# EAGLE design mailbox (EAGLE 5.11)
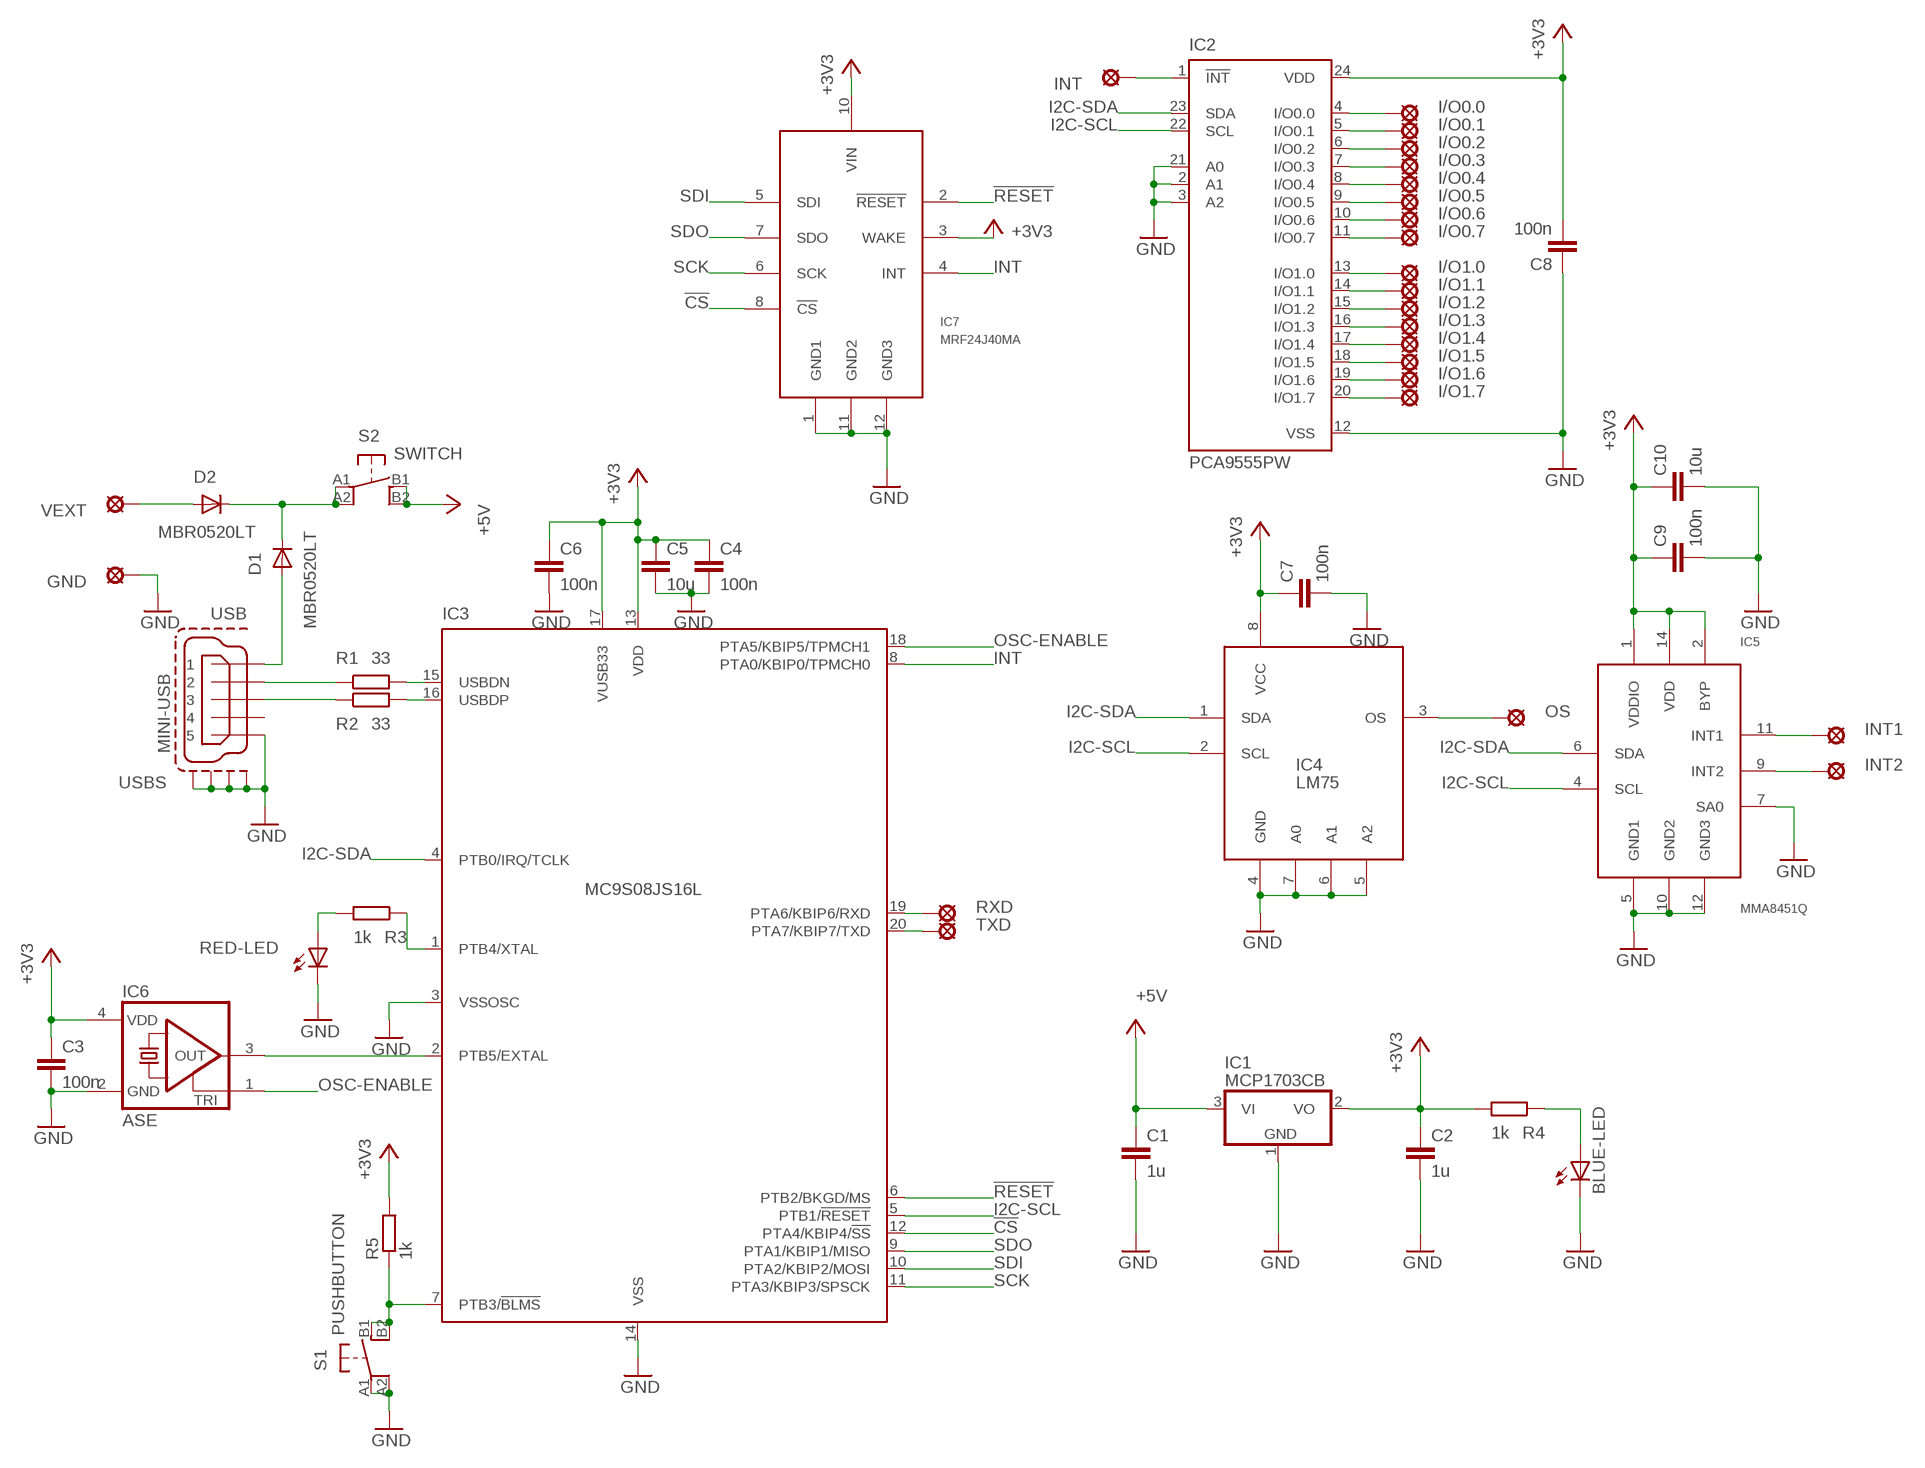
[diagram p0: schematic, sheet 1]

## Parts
BLUE-LED  LED5MM  [LED5MM]
C1  1u  C-EUC1210  [C1210]
C2  1u  C-EUC1210  [C1210]
C3  100n  C-EUC0603  [C0603]
C4  100n  C-EUC0603  [C0603]
C5  10u  C-EUC1210  [C1210]
C6  100n  C-EUC0603  [C0603]
C7  100n  C-EUC0603  [C0603]
C8  100n  C-EUC0603  [C0603]
C9  100n  C-EUC0603  [C0603]
C10  10u  C-EUC1210  [C1210]
D1  MBR0520LT  [SOD123]
D2  MBR0520LT  [SOD123]
GND  LSP10  [LSP10]
I/O0.0  LSP10  [LSP10]
I/O0.1  LSP10  [LSP10]
I/O0.2  LSP10  [LSP10]
I/O0.3  LSP10  [LSP10]
I/O0.4  LSP10  [LSP10]
I/O0.5  LSP10  [LSP10]
I/O0.6  LSP10  [LSP10]
I/O0.7  LSP10  [LSP10]
I/O1.0  LSP10  [LSP10]
I/O1.1  LSP10  [LSP10]
I/O1.2  LSP10  [LSP10]
I/O1.3  LSP10  [LSP10]
I/O1.4  LSP10  [LSP10]
I/O1.5  LSP10  [LSP10]
I/O1.6  LSP10  [LSP10]
I/O1.7  LSP10  [LSP10]
IC1  MCP1703CB  [SOT23]
IC2  PCA9555PW  [TSSOP24]
IC3  MC9S08JS16L  [SO-20DW]
IC4  LM75  [SOIC8]
IC5  MMA8451Q  [QFN16]
IC6  ASE  [ASE]
IC7  MRF24J40MA  [MRF24J40MA]
INT  LSP10  [LSP10]
INT1  LSP10  [LSP10]
INT2  LSP10  [LSP10]
OS  LSP10  [LSP10]
R1  33  R-EU_R0805  [R0805]
R2  33  R-EU_R0805  [R0805]
R3  1k  R-EU_R0805  [R0805]
R4  1k  R-EU_R0805  [R0805]
R5  1k  R-EU_R0805  [R0805]
RED-LED  LED5MM  [LED5MM]
RXD  LSP10  [LSP10]
S1  PUSHBUTTON  [PUSHBUTTON]
S2  SWITCH  [SWITCH]
TXD  LSP10  [LSP10]
USB  MINI-USB  MINI-USB-SHIELD-UX60-MB-5ST  [TYCO]
VEXT  LSP10  [LSP10]

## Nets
!CS: IC3.12(PTA4/KBIP4/!SS) IC7.8(!CS)
!RESET: IC3.6(PTB2/BKGD/MS) IC7.2(!RESET)
+3V3: C2.1 C3.1 C4.1 C5.1 C6.1 C7.1 C8.2 C9.1 C10.1 IC1.2(VO) IC2.24(VDD) IC3.13(VDD) IC3.17(VUSB33) IC4.8(VCC) IC5.1(VDDIO) IC5.2(BYP) IC5.14(VDD) IC6.4(VDD) IC7.3(WAKE) IC7.10(VIN) R4.2 R5.2
+5V: C1.1 IC1.3(VI) S2.B1(S) S2.B2(S1)
GND: BLUE-LED.K(C) C1.2 C2.2 C3.2 C4.2 C5.2 C6.2 C7.2 C8.1 C9.2 C10.2 GND.MP IC1.1(GND) IC2.2(A1) IC2.3(A2) IC2.12(VSS) IC2.21(A0) IC3.3(VSSOSC) IC3.14(VSS) IC4.4(GND) IC4.5(A2) IC4.6(A1) IC4.7(A0) IC5.5(GND1) IC5.7(SA0) IC5.10(GND2) IC5.12(GND3) IC6.2(GND) IC7.1(GND1) IC7.11(GND2) IC7.12(GND3) RED-LED.K(C) S1.A1(P) S1.A2(P1) USB.5 USB.M1(S1) USB.M2(S2) USB.M3(S3) USB.M4(S4)
I2C-SCL: IC2.22(SCL) IC3.5(PTB1/!RESET) IC4.2(SCL) IC5.4(SCL)
I2C-SDA: IC2.23(SDA) IC3.4(PTB0/IRQ/TCLK) IC4.1(SDA) IC5.6(SDA)
INT: IC3.8(PTA0/KBIP0/TPMCH0) IC7.4(INT)
N$1: R1.1 USB.2
N$2: IC3.2(PTB5/EXTAL) IC6.3(OUT)
N$3: IC3.1(PTB4/XTAL) R3.1
N$4: BLUE-LED.A R4.1
N$5: D1.A USB.1
N$6: R2.1 USB.3
N$7: IC3.15(USBDN) R1.2
N$8: IC3.16(USBDP) R2.2
N$9: R3.2 RED-LED.A
N$10: I/O0.0.MP IC2.4(I/O0.0)
N$11: I/O0.1.MP IC2.5(I/O0.1)
N$12: I/O0.2.MP IC2.6(I/O0.2)
N$13: IC3.19(PTA6/KBIP6/RXD) RXD.MP
N$14: IC3.20(PTA7/KBIP7/TXD) TXD.MP
N$15: I/O0.3.MP IC2.7(I/O0.3)
N$16: I/O0.4.MP IC2.8(I/O0.4)
N$17: I/O0.5.MP IC2.9(I/O0.5)
N$18: I/O0.6.MP IC2.10(I/O0.6)
N$19: I/O0.7.MP IC2.11(I/O0.7)
N$20: I/O1.0.MP IC2.13(I/O1.0)
N$21: I/O1.1.MP IC2.14(I/O1.1)
N$22: I/O1.2.MP IC2.15(I/O1.2)
N$23: I/O1.3.MP IC2.16(I/O1.3)
N$24: I/O1.4.MP IC2.17(I/O1.4)
N$25: I/O1.5.MP IC2.18(I/O1.5)
N$26: I/O1.6.MP IC2.19(I/O1.6)
N$27: I/O1.7.MP IC2.20(I/O1.7)
N$28: IC4.3(OS) OS.MP
N$29: IC5.11(INT1) INT1.MP
N$30: IC5.9(INT2) INT2.MP
N$31: IC2.1(!INT) INT.MP
N$33: D1.C D2.C S2.A1(P) S2.A2(P1)
N$34: D2.A VEXT.MP
N$35: IC3.7(PTB3/!BLMS) R5.1 S1.B1(S) S1.B2(S1)
OSC-ENABLE: IC3.18(PTA5/KBIP5/TPMCH1) IC6.1(TRI)
SCK: IC3.11(PTA3/KBIP3/SPSCK) IC7.6(SCK)
SDI: IC3.10(PTA2/KBIP2/MOSI) IC7.5(SDI)
SDO: IC3.9(PTA1/KBIP1/MISO) IC7.7(SDO)
Unconnected: USB.4

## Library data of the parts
BLUE-LED RED-LED = led:LED: LED
C1-C10 = rcl:C-EU: CAPACITOR, European symbol
D1 D2 = diode:MBR0520LT: SCHOTTKY BARRIER RECTIFIER
GND I/O0.0 I/O0.1-I/O0.7 I/O1.0 I/O1.1-I/O1.7 INT INT1 INT2 OS RXD TXD VEXT = solpad:LSP10: SOLDER PAD
IC1 = linear:MCP1703: 250 mA, 16V, Low Quiescent Current LDO Regulator Source: http://ww1.microchip.com/downloads/en/DeviceDoc/22049b.pdf
IC2 = micro-philips:PCA9555: 16-bit I2C and SMBus I/O port with interrupt Source: PCA9555_5.pdf; MPN: PCA9555PW; OC_FARNELL: 1408297; OC_NEWARK: 63K6069
IC3 = mailbox:MC9S08JS16L
IC4 = mailbox:LM75
IC5 = mailbox:MMA8451Q
IC6 = mailbox:ASE: 3.3Vdc CMOS SMD CRYSTAL CLOCK OSCILLATOR SOurce: www.abracon.com; OC_FARNELL: unknown; OC_NEWARK: unknown
IC7 = mailbox:MRF24J40MA
R1-R5 = rcl:R-EU_: RESISTOR, European symbol
S1 = mailbox:PUSHBUTTON
S2 = mailbox:SWITCH
USB = mailbox:MINI-USB-SHIELD-: MINI USB Connector Source: http://www.hirose.co.jp/cataloge_hp/e24000019.pdf; OC_FARNELL: unknown; OC_NEWARK: unknown

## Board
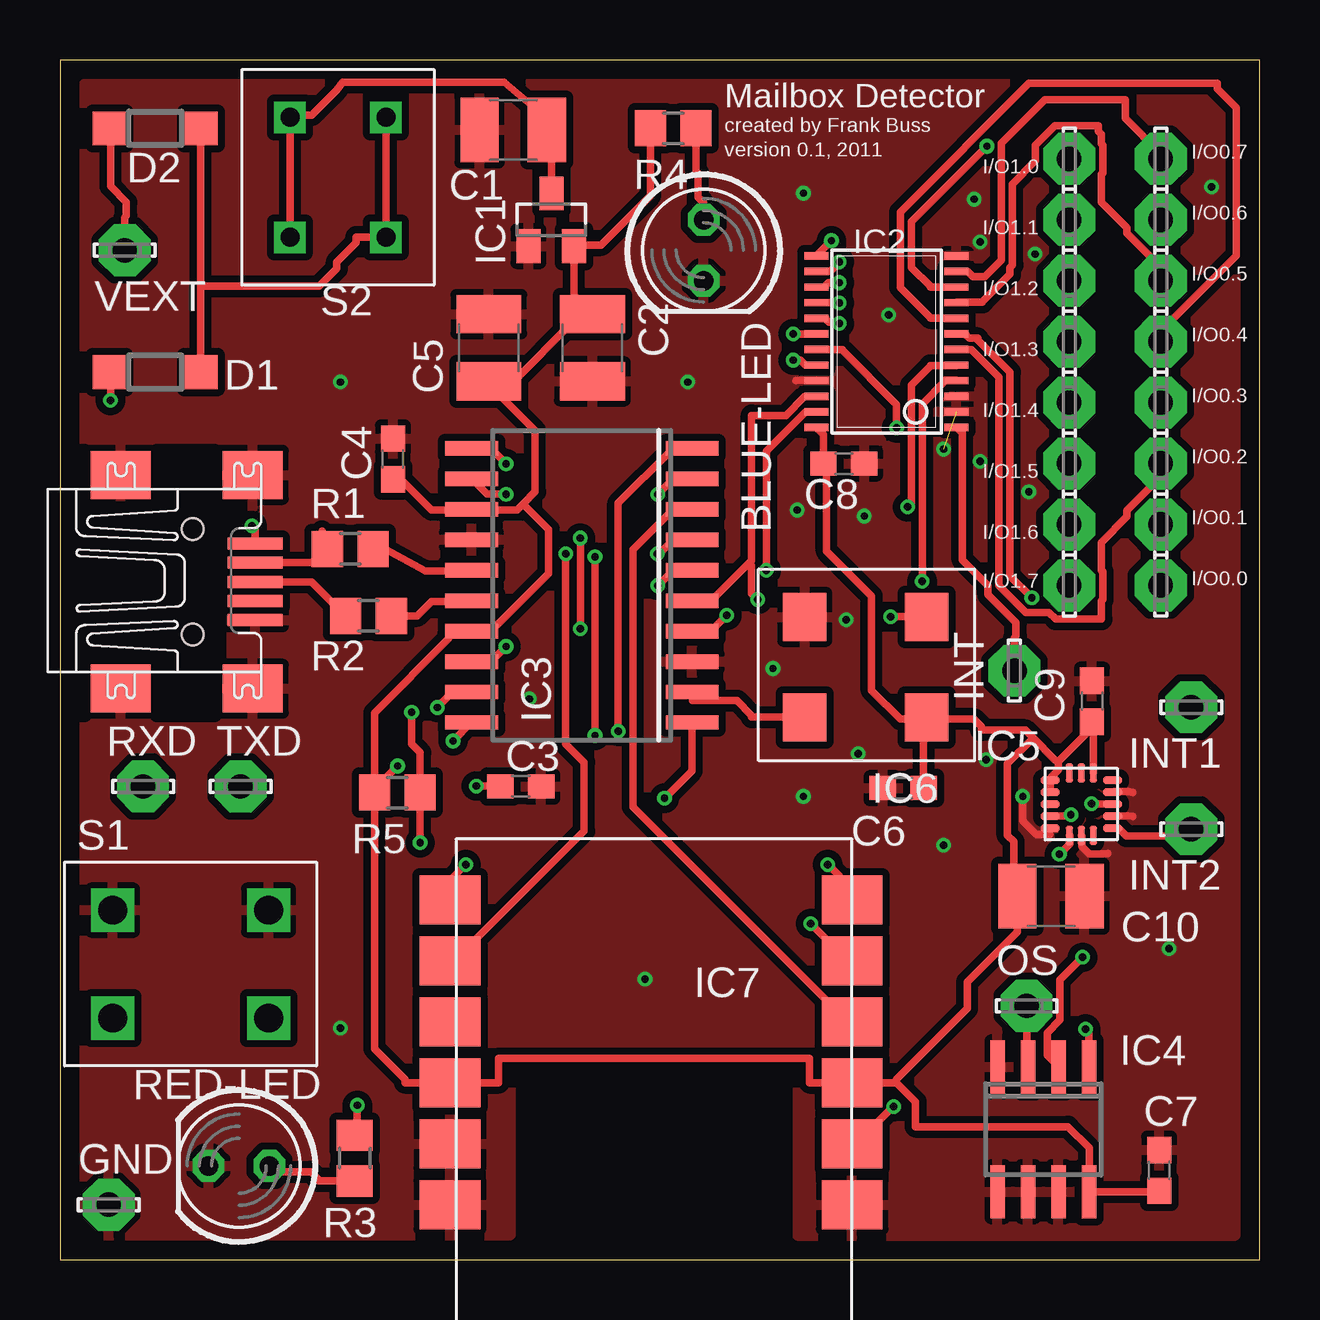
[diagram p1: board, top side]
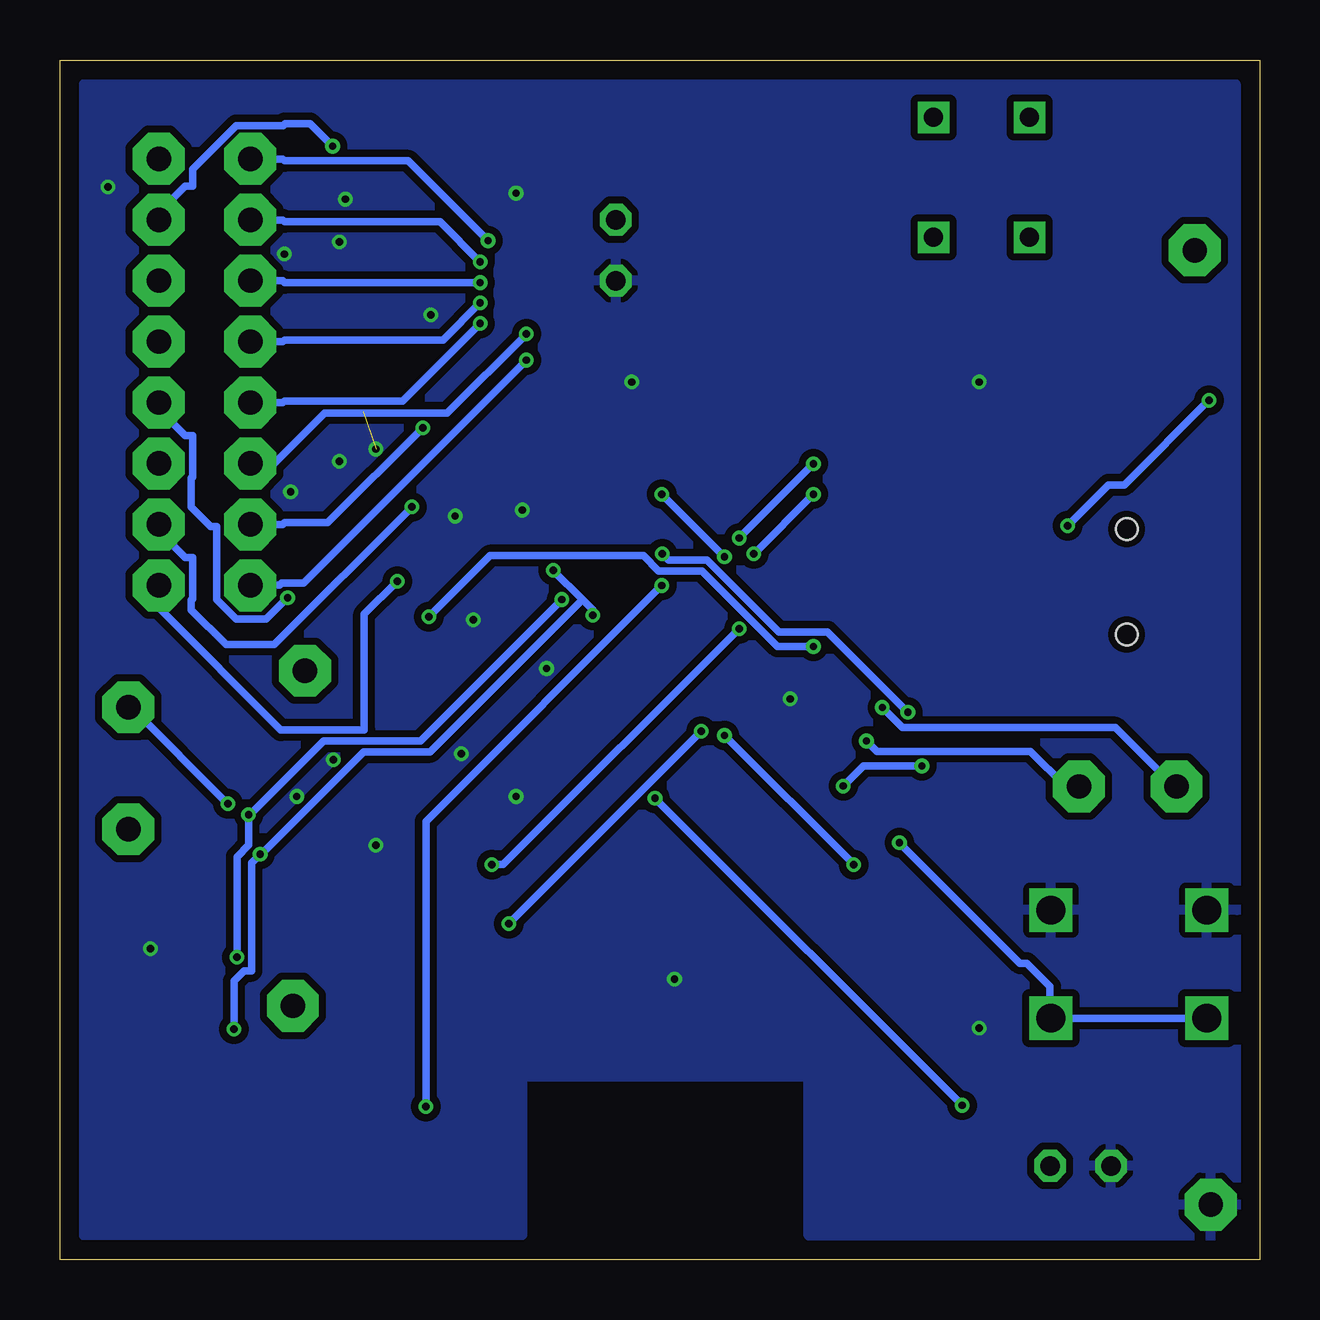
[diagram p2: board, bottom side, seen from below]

Size 50 x 50 mm. Coordinates in mm from the lower left corner, seen from the top.
Outline: 0,0 50,0 50,50 0,50 0,0
Copper layers (1*16): Top 0.035mm / dielectric 1.5mm / Bottom 0.035mm
Design rules "ITead_rule *": minimum track width 12mil, minimum drill 12mil, track to track 6mil, track to pad 6mil, pad to pad 6mil, via to via 6mil, smd to smd 0mil, copper to edge 10mil, drill to drill 10mil, minimum pad ring 10mil, minimum via ring 6mil, stop-mask expansion 2mil, vias tented up to drill 100mil, thermal gap 10mil

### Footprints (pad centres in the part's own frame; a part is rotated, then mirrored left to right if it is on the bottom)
LED5MM = drill 0.813 octagon: A -1.27,0; K 1.27,0
C1210 = smd 1.6 x 2.7: 1 -1.4,0; 2 1.4,0
C0603 = smd 1.1 x 1: 1 -0.85,0; 2 0.85,0
SOD123 = smd 1.4 x 1.4: A 1.9,0; C -1.9,0
LSP10 = drill 1.016 pad 2.159 octagon: MP 0,0
SOT23 = smd 1 x 1.4: 1 -0.95,-1.1; 2 0.95,-1.1; 3 0,1.1
TSSOP24 = smd 0.305 x 0.991: 1 -3.575,-2.918; 2 -2.925,-2.918; 3 -2.275,-2.918; 4 -1.625,-2.918; 5 -0.975,-2.918; 6 -0.325,-2.918; 7 0.325,-2.918; 8 0.975,-2.918; 9 1.625,-2.918; 10 2.275,-2.918; 11 2.925,-2.918; 12 3.575,-2.918; 13 3.575,2.918; 14 2.925,2.918; 15 2.275,2.918; 16 1.625,2.918; 17 0.975,2.918; 18 0.325,2.918; 19 -0.325,2.918; 20 -0.975,2.918; 21 -1.625,2.918; 22 -2.275,2.918; 23 -2.925,2.918; 24 -3.575,2.918
SO-20DW = smd 0.6 x 2.2: 1 -5.715,-4.6; 2 -4.445,-4.6; 3 -3.175,-4.6; 4 -1.905,-4.6; 5 -0.635,-4.6; 6 0.635,-4.6; 7 1.905,-4.6; 8 3.175,-4.6; 9 4.445,-4.6; 10 5.715,-4.6; 11 5.715,4.6; 12 4.445,4.6; 13 3.175,4.6; 14 1.905,4.6; 15 0.635,4.6; 16 -0.635,4.6; 17 -1.905,4.6; 18 -3.175,4.6; 19 -4.445,4.6; 20 -5.715,4.6
SOIC8 = smd 0.6 x 2.2: 1 -1.905,-2.6; 2 -0.635,-2.6; 3 0.635,-2.6; 4 1.905,-2.6; 5 1.905,2.6; 6 0.635,2.6; 7 -0.635,2.6; 8 -1.905,2.6
QFN16 = smd 0.8 x 0.3: 1 0.8,0.5; 2 0.8,1; 3 0.8,1.5; 4 0.8,2; 5 0.8,2.5; 9 -1.8,2.5; 10 -1.8,2; 11 -1.8,1.5; 12 -1.8,1; 13 -1.8,0.5 | smd 0.3 x 0.8: 6 0,2.8; 7 -0.5,2.8; 8 -1,2.8; 14 -1,0.2; 15 -0.5,0.2; 16 0,0.2
ASE = smd 1.8 x 2: 1 -2.5,-2.5; 2 2.58,-2.5; 3 2.58,1.7; 4 -2.5,1.7
MRF24J40MA = smd 2.54 x 2.032: 1 0,12.7; 2 0,10.16; 3 0,7.62; 4 0,5.08; 5 0,2.54; 6 0,0; 7 16.764,0; 8 16.764,2.54; 9 16.764,5.08; 10 16.764,7.62; 11 16.764,10.16; 12 16.764,12.7
R0805 = smd 1.3 x 1.5: 1 -0.95,0; 2 0.95,0
PUSHBUTTON = drill 1.2 square: A1 0,4.5; A2 6.5,4.5; B1 0,0; B2 6.5,0
SWITCH = drill 0.8 square: A1 -2,2; A2 -2,-3; B1 2,2; B2 2,-3
TYCO = smd 2.3 x 0.5: 1 2.9,1.75; 2 2.9,0.95; 3 2.9,0.15; 4 2.9,-0.65; 5 2.9,-1.45 | smd 2.5 x 2: M1 -2.7,-4.3; M2 -2.7,4.6; M3 2.8,4.6; M4 2.8,-4.3 | hole 0.9: 0.3,2.35; 0.3,-2.05

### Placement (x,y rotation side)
BLUE-LED  26.83,42.07 270 top
C1  18.89,47.08 180 top
C2  22.19,38.01 270 top
C3  19.21,19.72 0 top
C4  13.88,33.37 90 top
C5  17.87,38.01 90 top
C6  35.15,19.65 180 top
C7  45.81,3.72 90 top
C8  32.67,33.18 180 top
C9  43.02,23.27 90 top
C10  41.31,15.15 0 top
D1  3.97,36.99 180 top
D2  3.97,47.15 180 top
GND  2.03,2.29 0 top
I/O0.0  45.88,28.1 90 top
I/O0.1  45.88,30.64 90 top
I/O0.2  45.88,33.18 90 top
I/O0.3  45.88,35.72 90 top
I/O0.4  45.88,38.26 90 top
I/O0.5  45.88,40.8 90 top
I/O0.6  45.88,43.34 90 top
I/O0.7  45.88,45.88 90 top
I/O1.0  42.07,45.88 90 top
I/O1.1  42.07,43.34 90 top
I/O1.2  42.07,40.8 90 top
I/O1.3  42.07,38.26 90 top
I/O1.4  42.07,35.72 90 top
I/O1.5  42.07,33.18 90 top
I/O1.6  42.07,30.64 90 top
I/O1.7  42.07,28.1 90 top
IC1  20.48,43.34 0 top
IC2  34.45,38.26 90 top
IC3  21.75,28.1 90 top
IC4  40.99,5.43 180 top
IC5  42.07,20.48 180 top
IC6  33.62,24.29 180 top
IC7  33.02,14.99 180 top
INT  39.78,24.54 90 top
INT1  47.15,23.02 180 top
INT2  47.15,17.94 180 top
OS  40.29,10.57 0 top
R1  12.1,29.62 0 top
R2  12.86,26.83 0 top
R3  12.29,4.22 270 top
R4  25.56,47.15 180 top
R5  14.06,19.46 180 top
RED-LED  7.46,3.9 180 top
RXD  3.46,19.72 0 top
S1  2.19,10.07 0 top
S2  11.59,44.61 180 top
TXD  7.53,19.72 0 top
USB  5.24,28.1 0 top
VEXT  2.7,42.07 0 top

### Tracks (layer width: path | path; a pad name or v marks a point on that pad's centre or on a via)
!CS  (via drill 0.3)
  Top 0.305: v18.59,31.9 17.8,31.9 17.17,32.54 IC3.12 | v21.08,29.41 21.08,21.49 21.84,20.73 21.84,17.86 16.43,12.45 IC7.8
  Bottom 0.305: v21.08,29.41 v18.59,31.9
!RESET  (via drill 0.3)
  Top 0.305: v24.92,28.09 25.43,28.6 25.43,28.73 26.34,28.73 IC3.6 | v34.75,6.38 33.2,4.83 IC7.2
  Bottom 0.305: v24.92,28.09 34.75,18.26 v34.75,6.38
+3V3  (via drill 0.3)
  Top 0.305: C4.1 14.22,32.52 15.49,31.24 17.12,31.24 IC3.13 17.18,31.24 19.05,31.24 19.3,31.5 | C6.1 36,22.46 IC6.4 | IC2.24 31.82,34.4 C8.2 31.9,33.05 31.95,32.99 31.95,29.54 33.83,27.66 33.83,23.72 35.03,22.53 35.87,22.53 IC6.4 | IC5.14 43.07,22.37 C9.1 42.93,22.07 41.6,20.75 | C7.1 45.78,2.83 IC4.8 42.9,2.97 42.9,4.65 42.01,5.54 35.66,5.54 35.66,6.58 34.87,7.37 | 19.3,31.5 19.81,32 19.81,34.54 17.87,36.48 C5.1 18.44,36.12 18.44,36.14 21.84,39.55 C2.1 21.43,40.17 IC1.2 21.57,42.29 22.55,42.29 24.61,44.35 R4.2 | IC5.2 41.27,19.96 IC5.1 41.33,20.12 41.6,20.4 41.6,20.75 | 40.56,21.74 40.23,22.07 38.41,22.07 38.41,22.23 38.1,22.53 36.27,22.53 IC6.4 | 40.56,21.74 41.48,20.83 41.6,20.75 | 34.87,7.37 IC7.3 31.24,7.37 31.24,8.38 18.29,8.38 18.29,7.37 IC7.10 14.38,7.37 14.38,7.52 13.11,8.79 13.11,19.33 R5.2 | 34.87,7.37 34.87,7.52 37.82,10.46 37.82,11.58 39.9,13.66 39.9,15.14 C10.1 39.75,15.16 39.75,17.42 39.5,17.68 39.5,20.68 40.56,21.74 | v17.35,19.74 18.34,19.74 C3.1 | v14.07,20.57 13.13,19.63 13.13,19.48 R5.2 | R5.2 13.11,19.81 13.11,22.78 16.2,25.88 16.2,26.19 17.14,26.19 IC3.17 17.27,26.29 18.06,26.29 20.37,28.6 20.37,30.43 19.3,31.5
  Bottom 0.305: v17.35,19.74 16.51,20.57 v14.07,20.57
+5V
  Top 0.305: IC1.3 20.48,47.4 C1.1 20.17,47.68 18.52,49.07 11.79,49.07 11.53,48.74 10.49,47.7 9.7,47.7 S2.B2 9.6,47.6 9.6,42.62 S2.B1
GND  (via drill 0.3)  (1 unrouted)
  Top 0.305: IC5.7 42.6,17.65 42.6,17.22 42.9,16.92 43.46,16.92 43.67,16.93 | IC5.5 41.25,17.98 41.12,17.98 41.12,17.86 41.27,17.72 40.7,17.72 40.13,18.29 v40.13,19.3 | IC5.10 43.89,18.49 44.53,18.49 44.73,18.47 | IC5.12 43.89,19.48 43.92,19.48 43.94,19.51 44.53,19.51 44.73,19.47 | IC2.21 31.52,36.65 30.86,36.65 30.67,36.63
  other vias: 11.68,36.58 26.16,36.58 34.54,39.37 30.73,31.24 33.53,30.99 32.77,26.67 30.99,19.3 36.83,17.27 46.23,12.95 24.38,11.68 11.68,9.65 40.64,41.91 38.1,44.2 30.99,44.45 38.35,42.42 48.01,44.7 19.56,23.37 29.72,24.64 33.27,21.08 38.61,20.83 38.35,33.27 36.83,33.78 40.39,32
  pour Top (isolate 0.305): 1,1 18.8,1.02 18.8,7.62 30.73,7.62 30.73,1 49,1 49,49 1,49
  pour Bottom (isolate 0.305): 1,1 18.8,1 18.8,7.62 30.73,7.62 30.73,1.02 49,1 49,49 1,49
I2C-SCL  (via drill 0.3)
  Top 0.305: v42.14,18.54 42.14,18.49 IC5.4 | v42.62,12.6 41.68,11.66 41.68,9.98 41.15,9.45 41.15,8.51 41.6,8.05 IC4.2 | 28.73,29.03 27.18,27.48 26.36,27.48 IC3.5 | 28.73,29.03 28.83,29.13 28.83,35.18 30.25,35.18 31.04,35.97 31.52,35.97 IC2.22 | v29.08,27.51 28.83,27.76 28.83,28.93 28.73,29.03
  Bottom 0.305: v42.62,12.6 42.62,16.79 42.14,17.27 v42.14,18.54 42.01,18.62 39.01,21.61 34.98,21.61 v29.08,27.51
I2C-SDA  (via drill 0.3)
  Top 0.305: v41.66,16.89 42.09,17.32 42.09,17.68 IC5.6 | v42.75,9.6 42.88,9.47 42.88,8.05 IC4.1 | v29.44,28.73 29.44,33.71 31.06,35.33 IC2.23 | v27.79,26.85 27.15,26.21 26.36,26.21 IC3.4
  Bottom 0.305: v42.75,9.6 42.75,11.61 42.32,12.04 42.01,12.04 42.01,16.54 v41.66,16.89 41.53,16.97 37.34,21.16 34.57,21.16 28.22,27.51 | 28.22,27.51 27.79,27.08 v27.79,26.85 | 28.22,27.51 v29.44,28.73
INT
  Top 0.305: IC7.4 32.84,9.91 23.88,18.87 23.88,29.59 25.43,31.14 25.43,31.27 26.34,31.27 IC3.8
N$1
  Top 0.305: USB.2 10.51,29.05 10.92,29.46 10.92,30.36 R1.1
N$2
  Top 0.305: IC6.3 31.04,22.61 28.83,22.61 28.83,22.68 28.22,23.29 26.36,23.29 26.36,23.65 IC3.2
N$3  (via drill 0.3)
  Top 0.305: v12.39,6.43 12.39,5.28 R3.1 | v25.2,19.23 26.34,20.37 26.34,22.38 IC3.1
  Bottom 0.305: v12.39,6.43 v25.2,19.23
N$4
  Top 0.305: R4.1 26.52,45.36 26.59,45.29 26.59,44.27 26.82,44.04 26.82,43.36 BLUE-LED.A
N$5  (via drill 0.3)
  Top 0.305: v2.11,35.81 2.11,36.96 2.08,36.98 D1.A | v8,30.58 8.13,30.45 8.13,29.87 USB.1
  Bottom 0.305: v2.11,35.81 5.64,32.28 6.3,32.28 v8,30.58
N$6
  Top 0.305: USB.3 10.49,28.25 R2.1
N$7
  Top 0.305: R1.2 13.56,29.62 15.24,28.7 17.12,28.7 IC3.15
N$8
  Top 0.305: R2.2 14.89,26.83 15.49,27.43 17.12,27.43 IC3.16
N$9
  Top 0.305: R3.2 12.27,3.28 10.77,3.28 10.77,3.35 10.46,3.66 8.74,3.66 8.74,3.89 RED-LED.A
N$10  (via drill 0.3)
  Top 0.305: v35.94,28.27 35.94,35.66 36.91,36.63 36.91,36.65 37.36,36.65 IC2.4
  Bottom 0.305: v35.94,28.27 37.31,26.9 37.31,22.07 40.79,22.07 45.87,27.15 I/O0.0.MP
N$11  (via drill 0.3)
  Top 0.305: v35.33,31.37 35.48,31.52 35.48,36.45 36.27,37.24 36.27,37.26 37.36,37.26 IC2.5
  Bottom 0.305: v35.33,31.37 41.07,25.63 43.08,25.63 44.53,27.08 44.53,27.48 44.48,27.53 44.48,29.26 44.78,29.26 45.87,30.35 I/O0.1.MP
N$12
  Top 0.305: IC2.6 37.39,37.92 38,37.92 39.14,36.78 39.14,28.09 40.26,26.98 41.22,26.98 41.5,26.7 43.41,26.7 43.41,27.46 43.46,27.51 43.46,28.68 43.41,28.73 43.41,29.9 44.48,30.96 44.48,31.22 45.87,32.61 I/O0.2.MP
N$13  (via drill 0.3)
  Top 0.305: v15.72,23.01 16.2,23.5 16.2,23.65 17.14,23.65 IC3.19
  Bottom 0.305: v15.72,23.01 14.88,22.17 6.02,22.17 3.58,19.74 3.48,19.74 RXD.MP
N$14  (via drill 0.3)
  Top 0.305: v16.38,21.61 17.14,22.38 IC3.20
  Bottom 0.305: v16.38,21.61 15.95,21.18 9.55,21.18 8.1,19.74 7.54,19.74 TXD.MP
N$15  (via drill 0.3)
  Top 0.305: v40.51,27.58 39.6,28.5 39.6,36.98 38.25,38.33 38.25,38.41 37.9,38.41 37.77,38.53 37.77,38.58 37.39,38.58 IC2.7
  Bottom 0.305: v40.51,27.58 41.4,26.7 42.65,26.7 43.46,27.51 43.46,30.56 43.71,30.56 44.53,31.37 44.53,32.56 44.48,32.61 44.48,34.34 44.78,34.34 45.87,35.43 I/O0.3.MP
N$16
  Top 0.305: IC2.8 37.36,39.24 36.27,39.24 36.27,39.27 35.03,40.51 35.03,43.66 40.39,49.02 48.23,49.02 48.23,48.79 49.02,48.01 49.02,41.83 45.9,38.71 45.9,38.28 I/O0.4.MP
N$17
  Top 0.305: IC2.9 37.39,39.9 38.46,39.9 38.46,39.93 39.6,41.07 39.6,41.35 39.7,41.45 39.7,44.83 40.66,45.8 40.66,46.46 41.48,47.27 43.28,47.27 43.28,47.04 43.41,46.91 43.41,46.51 43.46,46.46 43.46,45.29 43.41,45.24 43.41,44.07 44.48,43 44.48,42.77 45.87,41.38 45.87,40.82 I/O0.5.MP
N$18  (via drill 0.3)
  Top 0.305: v38.63,46.41 35.48,43.26 35.48,41.35 36.27,40.56 36.27,40.54 IC2.10
  Bottom 0.305: v38.63,46.41 39.57,47.35 40.62,47.35 40.69,47.27 42.65,47.27 44.48,45.44 44.48,44.73 44.78,44.73 45.87,43.64 45.87,43.36 I/O0.6.MP
N$19
  Top 0.305: IC2.11 37.39,41.17 37.85,41.17 38.05,40.97 38.56,40.97 39.24,41.66 39.24,46.53 41.05,48.34 44.4,48.34 44.4,47.57 45.87,46.1 45.87,45.9 I/O0.7.MP
N$20  (via drill 0.3)
  Top 0.305: v32.16,42.47 31.55,41.86 IC2.13
  Bottom 0.305: v32.16,42.47 35.48,45.8 40.64,45.8 40.72,45.87 I/O1.0.MP
N$21  (via drill 0.3)
  Top 0.305: v32.49,41.58 32.11,41.2 31.55,41.2 IC2.14
  Bottom 0.305: v32.49,41.58 34.16,43.26 40.64,43.26 40.72,43.33 I/O1.1.MP
N$22  (via drill 0.3)
  Top 0.305: v32.49,40.72 32.03,40.72 31.9,40.59 31.9,40.54 31.55,40.54 IC2.15
  Bottom 0.305: v32.49,40.72 40.64,40.72 40.72,40.79 I/O1.2.MP
N$23  (via drill 0.3)
  Top 0.305: v32.49,39.88 31.55,39.88 IC2.16
  Bottom 0.305: v32.49,39.88 34.04,38.33 40.64,38.33 40.72,38.25 I/O1.3.MP
N$24  (via drill 0.3)
  Top 0.305: v32.49,39.01 32.49,39.06 32.05,39.06 31.93,39.19 31.93,39.22 31.55,39.22 IC2.17
  Bottom 0.305: v32.49,39.01 35.71,35.79 40.64,35.79 40.72,35.71 I/O1.4.MP
N$25  (via drill 0.3)
  Top 0.305: v30.56,38.58 IC2.18
  Bottom 0.305: v30.56,38.58 33.86,35.28 38.96,35.28 41.05,33.2 42.06,33.2 I/O1.5.MP
N$26  (via drill 0.3)
  Top 0.305: v34.87,34.67 34.87,35.64 32.61,37.9 32.61,37.92 31.55,37.92 IC2.19
  Bottom 0.305: v34.87,34.67 38.84,30.71 40.64,30.71 40.72,30.63 I/O1.6.MP
N$27  (via drill 0.3)
  Top 0.305: v30.56,37.49 30.86,37.49 31.06,37.29 IC2.20
  Bottom 0.305: v30.56,37.49 39.85,28.19 40.77,28.19 40.84,28.12 42.06,28.12 I/O1.7.MP
N$28
  Top 0.305: IC4.3 40.34,8.05 40.31,8.08 40.31,10.57 OS.MP
N$29  (via drill 0.3)
  Top 0.305: v43,19 43.87,19 IC5.11
  Bottom 0.305: v43,19 47.02,23.01 INT1.MP
N$30
  Top 0.305: IC5.9 43.89,17.98 44.12,17.98 44.45,17.65 47.14,17.65 INT2.MP
N$31
  Top 0.305: IC2.1 37.39,34.67 37.62,34.44 37.62,29.16 38.68,28.09 38.68,27.71 39.85,26.54 39.85,25.98 39.78,25.91 39.78,24.56 INT.MP
N$33
  Top 0.305: S2.A2 13.59,42.62 S2.A1 13.44,42.62 12.34,42.62 12.34,42.39 11.53,41.58 11.53,41.3 10.79,40.56 5.87,40.56 | 5.87,40.56 D2.C | 5.87,40.56 5.87,37.01 D1.C
N$34
  Top 0.305: D2.A 2.08,47.14 2.11,47.12 2.11,44.73 2.77,44.07 2.77,43.51 2.69,43.43 2.69,42.09 VEXT.MP
N$35  (via drill 0.3)
  Top 0.305: v15.01,17.37 R5.1 15.01,19.61 15.01,21.13 14.66,21.49 v14.66,22.81 | v24.89,29.41 24.97,29.41 25.43,29.87 25.43,30 26.34,30 IC3.7
  Bottom 0.305: v15.01,17.37 9.98,12.34 9.7,12.34 8.74,11.38 8.74,10.08 8.71,10.08 S1.B2 8.56,10.06 2.21,10.06 S1.B1 | v24.89,29.41 24.64,29.16 23.04,29.16 20.04,26.16 18.01,26.16 v14.66,22.81
OSC-ENABLE  (via drill 0.3)
  Top 0.305: v34.62,26.8 IC6.1 | v18.59,25.55 17.98,24.94 17.17,24.94 IC3.18
  Bottom 0.305: v34.62,26.8 32.08,29.34 25.68,29.34 25.04,28.7 23.24,28.7 20.09,25.55 v18.59,25.55
SCK  (via drill 0.3)
  Top 0.305: v18.59,33.17 18.09,33.68 18.09,33.81 17.17,33.81 IC3.11 | v21.69,26.29 v21.69,30.07 | v32,16.46 33.02,15.44 IC7.6
  Bottom 0.305: v21.69,30.07 v18.59,33.17 | v21.69,26.29 31.52,16.46 v32,16.46
SDI  (via drill 0.3)
  Top 0.305: v23.27,22.02 23.27,31.52 25.43,33.68 25.43,33.81 IC3.10 | v31.29,13.99 32.84,12.45 IC7.5
  Bottom 0.305: v31.29,13.99 v23.27,22.02
SDO  (via drill 0.3)
  Top 0.305: v24.92,31.9 25.43,32.41 25.43,32.54 26.34,32.54 IC3.9 | v22.3,21.84 v22.3,29.29 | v16.92,16.46 16.26,15.8 IC7.7
  Bottom 0.305: v22.3,29.29 v24.92,31.9 | v16.92,16.46 v22.3,21.84

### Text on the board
tNames: Mailbox Detector | created by Frank Buss | version 0.1, 2011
